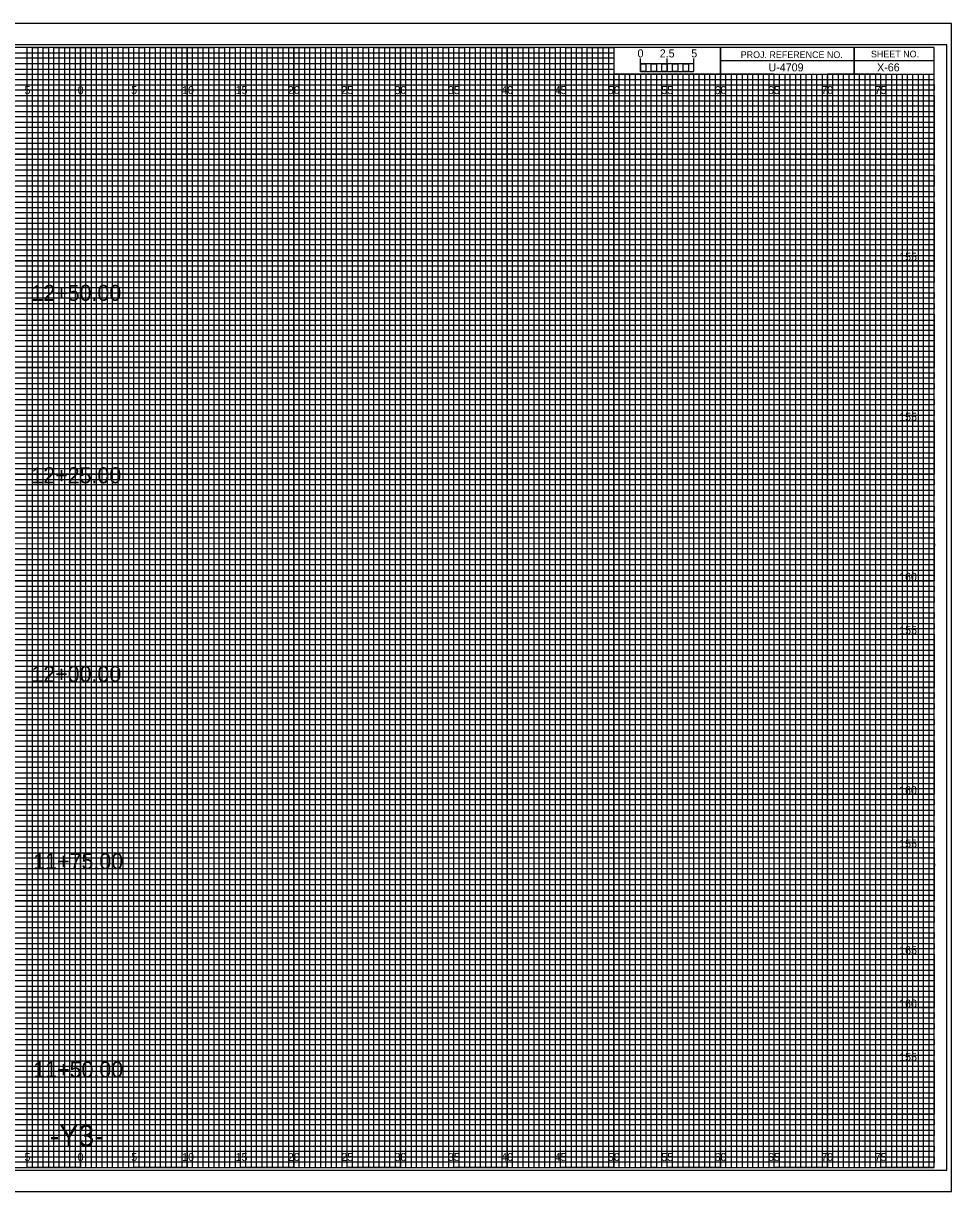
# Model space of a CAD drawing. Extents: x -7 to 162, y 108 to 217.
# Drawn here: x 74.6 to 161.7, y 107.7 to 217.2 of the extents above; entities that cross this region are included whole.
import ezdxf

# ---------------------------------------------------------------- set-up
doc = ezdxf.new("R2010")
doc.units = 0
for name, color, linetype in [('Prop CMT Conc Surface', 7, 'Continuous'), ('Prop CMT Pvmt Course 1', 7, 'Continuous'), ('Prop CMT Slope Grass', 7, 'Continuous'), ('Prop XS Alignment Label', 7, 'Continuous'), ('Prop XS Bar Scale Labels', 7, 'Continuous'), ('Prop XS Earthwork Shape', 7, 'Continuous'), ('Prop XS Elevation Labels', 7, 'Continuous'), ('Prop XS Hydro Elevations', 7, 'Continuous'), ('Prop XS Project Number', 7, 'Continuous'), ('Prop XS SE Text', 7, 'Continuous'), ('Prop XS Sheet Number', 7, 'Continuous'), ('Prop XS Side Slope Text', 7, 'Continuous'), ('Prop XS Station Labels', 7, 'Continuous'), ('Sheet Cutting Line CELL', 7, 'Continuous'), ('Sheet DOT Grid CELL', 7, 'Continuous'), ('Sheet Plot Border Inside CELL', 7, 'Continuous'), ('Sheet Plot Border Outside CELL', 7, 'Continuous')]:
    doc.layers.add(name, color=color, linetype=linetype)

msp = doc.modelspace()

# ---------------------------------------------------------------- linework, layer by layer
at = {"layer": 'Prop CMT Conc Surface'}
for p, q in [((75, 215), (70, 215)), ((75, 110), (75, 215)), ((85, 215), (80, 215)), ((80, 215), (80, 110)), ((85, 110), (85, 215)), ((95, 215), (90, 215)), ((90, 215), (90, 110)), ((95, 110), (95, 215)), ((105, 215), (100, 215)), ((100, 215), (100, 110)), ((105, 110), (105, 215)), ((115, 215), (110, 215)), ((110, 215), (110, 110)), ((115, 110), (115, 215)), ((125, 215), (120, 215)), ((120, 215), (120, 110)), ((125, 110), (125, 215)), ((130, 215), (130, 110)), ((135, 110), (135, 212.5)), ((145, 212.5), (140, 212.5)), ((140, 212.5), (140, 110)), ((145, 110), (145, 212.5)), ((155, 212.5), (150, 212.5)), ((150, 212.5), (150, 110)), ((155, 110), (155, 212.5)), ((80, 110), (75, 110)), ((90, 110), (85, 110)), ((100, 110), (95, 110)), ((110, 110), (105, 110)), ((120, 110), (115, 110)), ((130, 110), (125, 110)), ((140, 110), (135, 110)), ((150, 110), (145, 110)), ((160, 110), (155, 110)), ((160, 110), (160, 110))]:
    msp.add_line(p, q, dxfattribs=at)
for points in [[(0, 210), (160, 210), (160, 205), (0, 205)], [(0, 200), (160, 200), (160, 195), (0, 195)], [(0, 190), (160, 190), (160, 185), (0, 185)], [(0, 180), (160, 180), (160, 175), (0, 175)], [(0, 170), (160, 170), (160, 165), (0, 165)], [(0, 160), (160, 160), (160, 155), (0, 155)], [(0, 150), (160, 150), (160, 145), (0, 145)], [(0, 140), (160, 140), (160, 135), (0, 135)], [(0, 130), (160, 130), (160, 125), (0, 125)], [(0, 120), (160, 120), (160, 115), (0, 115)]]:
    msp.add_lwpolyline(points, dxfattribs=at)
at = {"layer": 'Prop CMT Slope Grass'}
for points in [[(72.5, 110), (77.5, 110), (77.5, 215), (82.5, 215), (82.5, 110), (87.5, 110), (87.5, 215), (92.5, 215), (92.5, 110), (97.5, 110), (97.5, 215), (102.5, 215), (102.5, 110), (107.5, 110), (107.5, 215), (112.5, 215), (112.5, 110), (117.5, 110), (117.5, 215), (122.5, 215), (122.5, 110), (127.5, 110), (127.5, 215), (129.97, 215), (130, 215), (130, 212.5), (132.5, 212.5), (132.5, 110), (137.5, 110), (137.5, 212.5), (142.5, 212.5), (142.5, 110), (147.5, 110), (147.5, 212.5), (152.5, 212.5), (152.5, 110), (157.5, 110), (157.5, 212.5)], [(0, 212.5), (137.5, 212.5)], [(0, 202.5), (160, 202.5), (160, 207.5), (0, 207.5)], [(0, 192.5), (160, 192.5), (160, 197.5), (0, 197.5)], [(0, 182.5), (160, 182.5), (160, 187.5), (0, 187.5)], [(0, 172.5), (160, 172.5), (160, 177.5), (0, 177.5)], [(0, 162.5), (160, 162.5), (160, 167.5), (0, 167.5)], [(0, 152.5), (160, 152.5), (160, 157.5), (0, 157.5)], [(0, 142.5), (160, 142.5), (160, 147.5), (0, 147.5)], [(0, 132.5), (160, 132.5), (160, 137.5), (0, 137.5)], [(0, 122.5), (160, 122.5), (160, 127.5), (0, 127.5)], [(0, 112.5), (160, 112.5), (160, 117.5), (0, 117.5)]]:
    msp.add_lwpolyline(points, dxfattribs=at)
at = {"layer": 'Prop XS Earthwork Shape'}
for p, q in [((132.5, 212.75), (132.5, 213.95)), ((132.5, 213.45), (132.5, 213.95)), ((135, 212.75), (135, 213.95)), ((137.5, 212.75), (137.5, 213.95)), ((137.5, 213.45), (137.5, 213.95))]:
    msp.add_line(p, q, dxfattribs=at)
for points in [[(137.5, 213.45), (132.5, 213.45), (132.5, 212.75), (137.5, 212.75)], [(132.5, 213.45), (133, 213.45), (133, 212.75), (132.5, 212.75)], [(133.5, 213.45), (134, 213.45), (134, 212.75), (133.5, 212.75)], [(134.5, 213.45), (135, 213.45), (135, 212.75), (134.5, 212.75)], [(135.5, 213.45), (136, 213.45), (136, 212.75), (135.5, 212.75)], [(136.5, 213.45), (137, 213.45), (137, 212.75), (136.5, 212.75)]]:
    msp.add_lwpolyline(points, close=True, dxfattribs=at)
at = {"layer": 'Prop XS Hydro Elevations'}
for p, q in [((133.5, 212.5), (133, 212.5)), ((133, 212.5), (133, 110)), ((133.5, 110), (133.5, 212.5)), ((134.5, 212.5), (134, 212.5)), ((134, 212.5), (134, 110)), ((134.5, 110), (134.5, 212.5)), ((133, 110), (132.5, 110)), ((134, 110), (133.5, 110))]:
    msp.add_line(p, q, dxfattribs=at)
for points in [[(75, 110), (75.5, 110), (75.5, 215), (76, 215), (76, 110)], [(76, 110), (76.5, 110), (76.5, 215), (77, 215), (77, 110)], [(77.5, 110), (78, 110), (78, 215), (78.5, 215), (78.5, 110)], [(78.5, 110), (79, 110), (79, 215), (79.5, 215), (79.5, 110)], [(80, 110), (80.5, 110), (80.5, 215), (81, 215), (81, 110)], [(81, 110), (81.5, 110), (81.5, 215), (82, 215), (82, 110)], [(82.5, 110), (83, 110), (83, 215), (83.5, 215), (83.5, 110)], [(83.5, 110), (84, 110), (84, 215), (84.5, 215), (84.5, 110)], [(85, 110), (85.5, 110), (85.5, 215), (86, 215), (86, 110)], [(86, 110), (86.5, 110), (86.5, 215), (87, 215), (87, 110)], [(87.5, 110), (88, 110), (88, 215), (88.5, 215), (88.5, 110)], [(88.5, 110), (89, 110), (89, 215), (89.5, 215), (89.5, 110)], [(90, 110), (90.5, 110), (90.5, 215), (91, 215), (91, 110)], [(91, 110), (91.5, 110), (91.5, 215), (92, 215), (92, 110)], [(92.5, 110), (93, 110), (93, 215), (93.5, 215), (93.5, 110)], [(93.5, 110), (94, 110), (94, 215), (94.5, 215), (94.5, 110)], [(95, 110), (95.5, 110), (95.5, 215), (96, 215), (96, 110)], [(96, 110), (96.5, 110), (96.5, 215), (97, 215), (97, 110)], [(97.5, 110), (98, 110), (98, 215), (98.5, 215), (98.5, 110)], [(98.5, 110), (99, 110), (99, 215), (99.5, 215), (99.5, 110)], [(100, 110), (100.5, 110), (100.5, 215), (101, 215), (101, 110)], [(101, 110), (101.5, 110), (101.5, 215), (102, 215), (102, 110)], [(102.5, 110), (103, 110), (103, 215), (103.5, 215), (103.5, 110)], [(103.5, 110), (104, 110), (104, 215), (104.5, 215), (104.5, 110)], [(105, 110), (105.5, 110), (105.5, 215), (106, 215), (106, 110)], [(106, 110), (106.5, 110), (106.5, 215), (107, 215), (107, 110)], [(107.5, 110), (108, 110), (108, 215), (108.5, 215), (108.5, 110)], [(108.5, 110), (109, 110), (109, 215), (109.5, 215), (109.5, 110)], [(110, 110), (110.5, 110), (110.5, 215), (111, 215), (111, 110)], [(111, 110), (111.5, 110), (111.5, 215), (112, 215), (112, 110)], [(112.5, 110), (113, 110), (113, 215), (113.5, 215), (113.5, 110)], [(113.5, 110), (114, 110), (114, 215), (114.5, 215), (114.5, 110)], [(115, 110), (115.5, 110), (115.5, 215), (116, 215), (116, 110)], [(116, 110), (116.5, 110), (116.5, 215), (117, 215), (117, 110)], [(117.5, 110), (118, 110), (118, 215), (118.5, 215), (118.5, 110)], [(118.5, 110), (119, 110), (119, 215), (119.5, 215), (119.5, 110)], [(120, 110), (120.5, 110), (120.5, 215), (121, 215), (121, 110)], [(121, 110), (121.5, 110), (121.5, 215), (122, 215), (122, 110)], [(122.5, 110), (123, 110), (123, 215), (123.5, 215), (123.5, 110)], [(123.5, 110), (124, 110), (124, 215), (124.5, 215), (124.5, 110)], [(125, 110), (125.5, 110), (125.5, 215), (126, 215), (126, 110)], [(126, 110), (126.5, 110), (126.5, 215), (127, 215), (127, 110)], [(127.5, 110), (128, 110), (128, 215), (128.5, 215), (128.5, 110)], [(128.5, 110), (129, 110), (129, 215), (129.5, 215), (129.5, 110)], [(130, 110), (130.5, 110), (130.5, 212.5), (131.01, 212.5), (131.01, 110)], [(131, 110), (131.5, 110), (131.5, 212.5), (132, 212.5), (132, 110)], [(135, 110), (135.49, 110), (135.49, 212.5), (136, 212.5), (136, 110)], [(136, 110), (136.5, 110), (136.5, 212.5), (137.03, 212.5), (137.03, 110)], [(137.5, 110), (138, 110), (138, 212.5), (138.5, 212.5), (138.5, 110)], [(138.5, 110), (139, 110), (139, 212.5), (139.5, 212.5), (139.5, 110)], [(140, 110), (140.5, 110), (140.5, 212.5), (141, 212.5), (141, 110)], [(141, 110), (141.5, 110), (141.5, 212.5), (142, 212.5), (142, 110)], [(142.5, 110), (143, 110), (143, 212.5), (143.5, 212.5), (143.5, 110)], [(143.5, 110), (144, 110), (144, 212.5), (144.5, 212.5), (144.5, 110)], [(145, 110), (145.5, 110), (145.5, 212.5), (146, 212.5), (146, 110)], [(146, 110), (146.5, 110), (146.5, 212.5), (147, 212.5), (147, 110)], [(147.5, 110), (148, 110), (148, 212.5), (148.5, 212.5), (148.5, 110)], [(148.5, 110), (149, 110), (149, 212.5), (149.5, 212.5), (149.5, 110)], [(150, 110), (150.5, 110), (150.5, 212.5), (151, 212.5), (151, 110)], [(151, 110), (151.5, 110), (151.5, 212.5), (152, 212.5), (152, 110)], [(152.5, 110), (153, 110), (153, 212.5), (153.5, 212.5), (153.5, 110)], [(153.5, 110), (154, 110), (154, 212.5), (154.5, 212.5), (154.5, 110)], [(155, 110), (155.5, 110), (155.5, 212.5), (156, 212.5), (156, 110)], [(156, 110), (156.5, 110), (156.5, 212.5), (157, 212.5), (157, 110)], [(157.5, 110), (158, 110), (158, 212.5), (158.5, 212.5), (158.5, 110)], [(158.5, 110), (159, 110), (159, 212.5), (159.5, 212.5), (159.5, 110)]]:
    msp.add_lwpolyline(points, dxfattribs=at)
at = {"layer": 'Prop XS SE Text'}
for p, q in [((0, 214.5), (130, 214.5)), ((130, 213.99), (0, 213.99)), ((130, 214.5), (130, 213.99)), ((0, 213.5), (130, 213.5)), ((130, 212.94), (0, 212.94)), ((130, 213.5), (130, 212.94)), ((0, 212), (160, 212))]:
    msp.add_line(p, q, dxfattribs=at)
for points in [[(0, 211.5), (135, 211.5), (160, 211.5), (160, 211), (0, 211)], [(0, 210.5), (160, 210.5), (160, 209.5), (0, 209.5)], [(0, 209), (160, 209), (160, 208.5), (0, 208.49)], [(0, 208), (160, 208), (160, 207), (0, 207)], [(0, 206.5), (160, 206.5), (160, 206), (0, 206)], [(0, 205.5), (160, 205.5), (160, 204.5), (0, 204.5)], [(0, 204), (160, 204), (160, 203.5), (0, 203.5)], [(0, 203), (160, 203), (160, 202), (0, 202)], [(0, 201.5), (160, 201.5), (160, 201), (0, 201)], [(0, 200.5), (160, 200.5), (160, 199.5), (0, 199.5)], [(0, 199), (160, 199), (160, 198.5), (0, 198.5)], [(0, 198), (160, 198), (160, 196.97), (160, 196.5), (160, 196), (0, 196)], [(0, 197), (160, 197), (160, 196.5), (0, 196.5)], [(0, 195.5), (160, 195.5), (160, 194.5), (0, 194.52)], [(0, 194.52), (160, 194.5), (160, 194), (0, 194)], [(0, 193.5), (160, 193.5), (160, 193), (0, 193)], [(0, 192), (160, 192), (160, 191.5), (0, 191.5)], [(0, 191), (160, 191), (160, 190.5), (0, 190.5)], [(-0.04, 189.44), (160, 189.44), (160, 188.94), (-0.04, 188.94)], [(0, 188.5), (160, 188.5), (160, 188), (0, 188)], [(0, 187), (160, 187), (160, 186.5), (0, 186.5)], [(0, 186), (160, 186), (160, 185.5), (0, 185.5)], [(0, 184.5), (160, 184.5), (160, 184), (0, 184)], [(0, 183.5), (160, 183.5), (160, 183), (0, 183)], [(0, 182), (160, 182), (160, 181.5), (0, 181.5)], [(0, 181), (160, 181), (160, 180.5), (0, 180.5)], [(0, 179.5), (160, 179.5), (160, 178.99), (0, 179)], [(0, 178.5), (160, 178.5), (160, 178), (0, 178)], [(0, 177), (160, 177), (160, 176.5), (0, 176.5)], [(0, 176), (160, 176), (160, 175.5), (0, 175.5)], [(0, 174.5), (160, 174.5), (160, 174), (0, 174)], [(0, 173.5), (160, 173.5), (160, 173), (0, 173)], [(0, 172), (160, 172), (160, 171.5), (0, 171.5)], [(0, 171), (160, 171), (160, 170.5), (0, 170.5)], [(0, 169.5), (160, 169.5), (160, 169), (0, 169)], [(0, 168.5), (160.03, 168.46), (160, 168), (0, 168)], [(0, 167), (160, 167), (160, 166.5), (0, 166.5)], [(0, 166), (160, 166), (160, 165.5), (0, 165.5)], [(0, 164.5), (160, 164.5), (160, 164), (0, 164)], [(0, 163.5), (160, 163.5), (160, 163), (0, 163)], [(0, 162), (160, 162), (160, 161.5), (0, 161.5)], [(0, 161), (160, 161), (160, 160.5), (0, 160.5)], [(0, 159.5), (160, 159.5), (160, 159), (0, 159)], [(0, 158.5), (160, 158.5), (160, 158), (0, 158)], [(0, 157), (160, 157), (160, 156.5), (0, 156.5)], [(0, 156), (160, 156), (160, 155.5), (0, 155.5)], [(0, 154.5), (160, 154.5), (160, 154), (0, 154)], [(0, 153.5), (160, 153.5), (160, 153), (0, 153)], [(0, 152), (160, 152), (160, 151.5), (0, 151.5)], [(0, 151), (160, 151), (160, 150.5), (0, 150.5)], [(0, 149.5), (160, 149.5), (160, 148.99), (0, 149)], [(0, 148.5), (160, 148.5), (160, 148), (0, 148)], [(0, 147), (160, 147), (160, 146.5), (0, 146.5)], [(0, 146), (160, 146), (160, 145.5), (0, 145.5)], [(0, 144.5), (160, 144.5), (160, 144), (0, 144)], [(0, 143.5), (160, 143.5), (160, 143), (0, 143)], [(0, 142), (160, 142), (160, 141.5), (0, 141.5)], [(0, 141), (160, 141), (160, 140.5), (0, 140.5)], [(0, 139.5), (160, 139.5), (160, 139), (0, 139)], [(0, 138.5), (160.03, 138.46), (160, 138), (0, 138)], [(0, 137), (160, 137), (160, 136.5), (0, 136.5)], [(0, 136), (160, 136), (160, 135.5), (0, 135.5)], [(0, 134.5), (160, 134.5), (160, 134), (0, 134)], [(0, 133.5), (160, 133.5), (160, 133), (0, 133)], [(0, 132), (160, 132), (160, 131.5), (0, 131.5)], [(0, 131), (160, 131), (160, 130.5), (0, 130.5)], [(0, 129.5), (160, 129.5), (160, 129), (0, 129)], [(0, 128.5), (160, 128.5), (160, 128), (0, 128)], [(0, 127), (160, 127), (160, 126.5), (0, 126.5)], [(0, 126), (160, 126), (160, 125.5), (0, 125.5)], [(0, 124.5), (160, 124.5), (160, 124), (0, 124)], [(0, 123.5), (160, 123.5), (160, 123), (0, 123)], [(0, 122), (160, 122), (160, 121.5), (0, 121.5)], [(0, 121), (160, 121), (160, 120.5), (0, 120.5)], [(0, 119.5), (160, 119.5), (160, 119), (0, 119)], [(0, 118.5), (160, 118.5), (160, 118), (0, 118)], [(0, 117), (160, 117), (160, 116.5), (0, 116.5)], [(0, 116), (160, 116), (160, 115.5), (0, 115.5)], [(0, 114.5), (160, 114.5), (160, 114), (0, 114)], [(0, 113.5), (160, 113.5), (160, 113), (0, 113)], [(0, 112), (160, 112), (160, 111.5), (0, 111.5)], [(0, 111), (160, 111), (160, 110.5), (0, 110.5)]]:
    msp.add_lwpolyline(points, dxfattribs=at)
at = {"layer": 'Prop XS Side Slope Text'}
for p, q in [((152.5, 215), (152.5, 212.5)), ((152.5, 212.5), (152.5, 215)), ((160, 213.75), (140, 213.75)), ((140, 213.75), (140, 212.5)), ((140, 212.5), (160, 212.5))]:
    msp.add_line(p, q, dxfattribs=at)
for points in [[(160, 215), (0, 215), (0, 110), (160, 110)], [(140, 215), (130, 215), (130, 212.52), (140, 212.52)], [(160, 215), (140, 215), (140, 212.5), (160, 212.5)]]:
    msp.add_lwpolyline(points, close=True, dxfattribs=at)
at = {"layer": 'Sheet Cutting Line CELL'}
for p, q in [((161.65, 217.25), (-6.7, 217.25)), ((-6.7, 107.75), (161.65, 107.75))]:
    msp.add_line(p, q, dxfattribs=at)
at = {"layer": 'Sheet DOT Grid CELL'}
for p, q in [((75, 110), (75, 215)), ((80, 110), (80, 215)), ((85, 110), (85, 215)), ((90, 110), (90, 215)), ((95, 110), (95, 215)), ((100, 110), (100, 215)), ((105, 110), (105, 215)), ((110, 110), (110, 215)), ((115, 110), (115, 215)), ((120, 110), (120, 215)), ((125, 110), (125, 215)), ((130, 110), (130, 212.34)), ((135, 110), (135, 212.34)), ((140, 110), (140, 212.34)), ((145, 110), (145, 212.34)), ((150, 110), (150, 212.34)), ((155, 110), (155, 212.34)), ((0, 210), (160, 210)), ((0, 205), (160, 205)), ((0, 200), (160, 200)), ((0, 195), (160, 195)), ((0, 190), (160, 190)), ((0, 185), (160, 185)), ((0, 180), (160, 180)), ((0, 175), (160, 175)), ((0, 170), (160, 170)), ((0, 165), (160, 165)), ((0, 160), (160, 160)), ((0, 155), (160, 155)), ((0, 150), (160, 150)), ((0, 145), (160, 145)), ((0, 140), (160, 140)), ((0, 135), (160, 135)), ((0, 130), (160, 130)), ((0, 125), (160, 125)), ((0, 120), (160, 120)), ((0, 115), (160, 115))]:
    msp.add_line(p, q, dxfattribs=at)
at = {"layer": 'Sheet Plot Border Inside CELL'}
msp.add_lwpolyline([(-5.4, 109.75), (161.2, 109.75), (161.2, 215.25), (-5.4, 215.25)], close=True, dxfattribs=at)
at = {"layer": 'Sheet Plot Border Outside CELL'}
msp.add_lwpolyline([(-6.7, 107.75), (161.65, 107.75), (161.65, 217.25), (-6.7, 217.25)], close=True, dxfattribs=at)

# ---------------------------------------------------------------- texts
at = {"layer": 'Prop CMT Pvmt Course 1'}
for s, p in [('5', (74.74, 210.62)), ('0', (79.73, 210.62)), ('0', (79.73, 210.62)), ('5', (84.74, 210.62)), ('10', (89.52, 210.62)), ('15', (94.53, 210.62)), ('20', (99.43, 210.62)), ('25', (104.44, 210.62)), ('30', (109.43, 210.62)), ('35', (114.44, 210.62)), ('40', (119.43, 210.62)), ('45', (124.44, 210.62)), ('50', (129.43, 210.62)), ('55', (134.44, 210.62)), ('60', (139.43, 210.62)), ('65', (144.44, 210.62)), ('70', (149.43, 210.62)), ('75', (154.44, 210.62)), ('5', (74.74, 110.62)), ('0', (79.73, 110.62)), ('0', (79.73, 110.62)), ('5', (84.74, 110.62)), ('10', (89.52, 110.62)), ('15', (94.53, 110.62)), ('20', (99.43, 110.62)), ('25', (104.44, 110.62)), ('30', (109.43, 110.62)), ('35', (114.44, 110.62)), ('40', (119.43, 110.62)), ('45', (124.44, 110.62)), ('50', (129.43, 110.62)), ('55', (134.44, 110.62)), ('60', (139.43, 110.62)), ('65', (144.44, 110.62)), ('70', (149.43, 110.62)), ('75', (154.44, 110.62))]:
    msp.add_text(s, height=0.75, dxfattribs=at).set_placement(p)
at = {"layer": 'Prop XS Alignment Label'}
msp.add_text('-Y3-', height=2, dxfattribs=at).set_placement((77.12, 112))
at = {"layer": 'Prop XS Bar Scale Labels'}
for s, p in [('2.5', (134.29, 214.06)), ('5', (137.24, 214.06))]:
    msp.add_text(s, height=0.75, dxfattribs=at).set_placement(p)
at = {"layer": 'Prop XS Earthwork Shape'}
msp.add_text('0', height=0.75, dxfattribs=at).set_placement((132.21, 214.06))
at = {"layer": 'Prop XS Elevation Labels'}
for s, p in [('155', (156.73, 195)), ('155', (156.73, 180)), ('160', (156.72, 165)), ('155', (156.73, 160)), ('160', (156.72, 145)), ('155', (156.73, 140)), ('165', (156.73, 130)), ('160', (156.72, 125)), ('155', (156.73, 120))]:
    msp.add_text(s, height=0.75, dxfattribs=at).set_placement(p)
at = {"layer": 'Prop XS Project Number'}
msp.add_text('U-4709', height=0.75, dxfattribs=at).set_placement((144.48, 212.75))
at = {"layer": 'Prop XS Sheet Number'}
msp.add_text('X-66', height=0.75, dxfattribs=at).set_placement((154.66, 212.75))
at = {"layer": 'Prop XS Side Slope Text'}
for s, p in [('PROJ. REFERENCE NO.', (141.88, 214)), ('SHEET NO.', (154.09, 214.06))]:
    msp.add_text(s, height=0.625, dxfattribs=at).set_placement(p)
at = {"layer": 'Prop XS Station Labels'}
for s, p in [('12+50.00', (75.39, 191.24)), ('12+25.00', (75.39, 174.14)), ('12+00.00', (75.39, 155.52)), ('11+75.00', (75.57, 137.97)), ('11+50.00', (75.57, 118.45))]:
    msp.add_text(s, height=1.5, dxfattribs=at).set_placement(p)

doc.saveas('drawing.dxf')
